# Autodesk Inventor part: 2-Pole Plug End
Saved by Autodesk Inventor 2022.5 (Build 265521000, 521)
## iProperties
Created: 2025-02
Part Number: 2-Pole Plug End
Material: Generic
Document SubType Name: Modeling
Designer: AdminForWorker
Density: 1 g/cm^3
Appearance: Default
Title: 2-Pole Plug End
Author: AdminForWorker
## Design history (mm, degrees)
feature "2-Pole Plug End"
body "Solid1"
